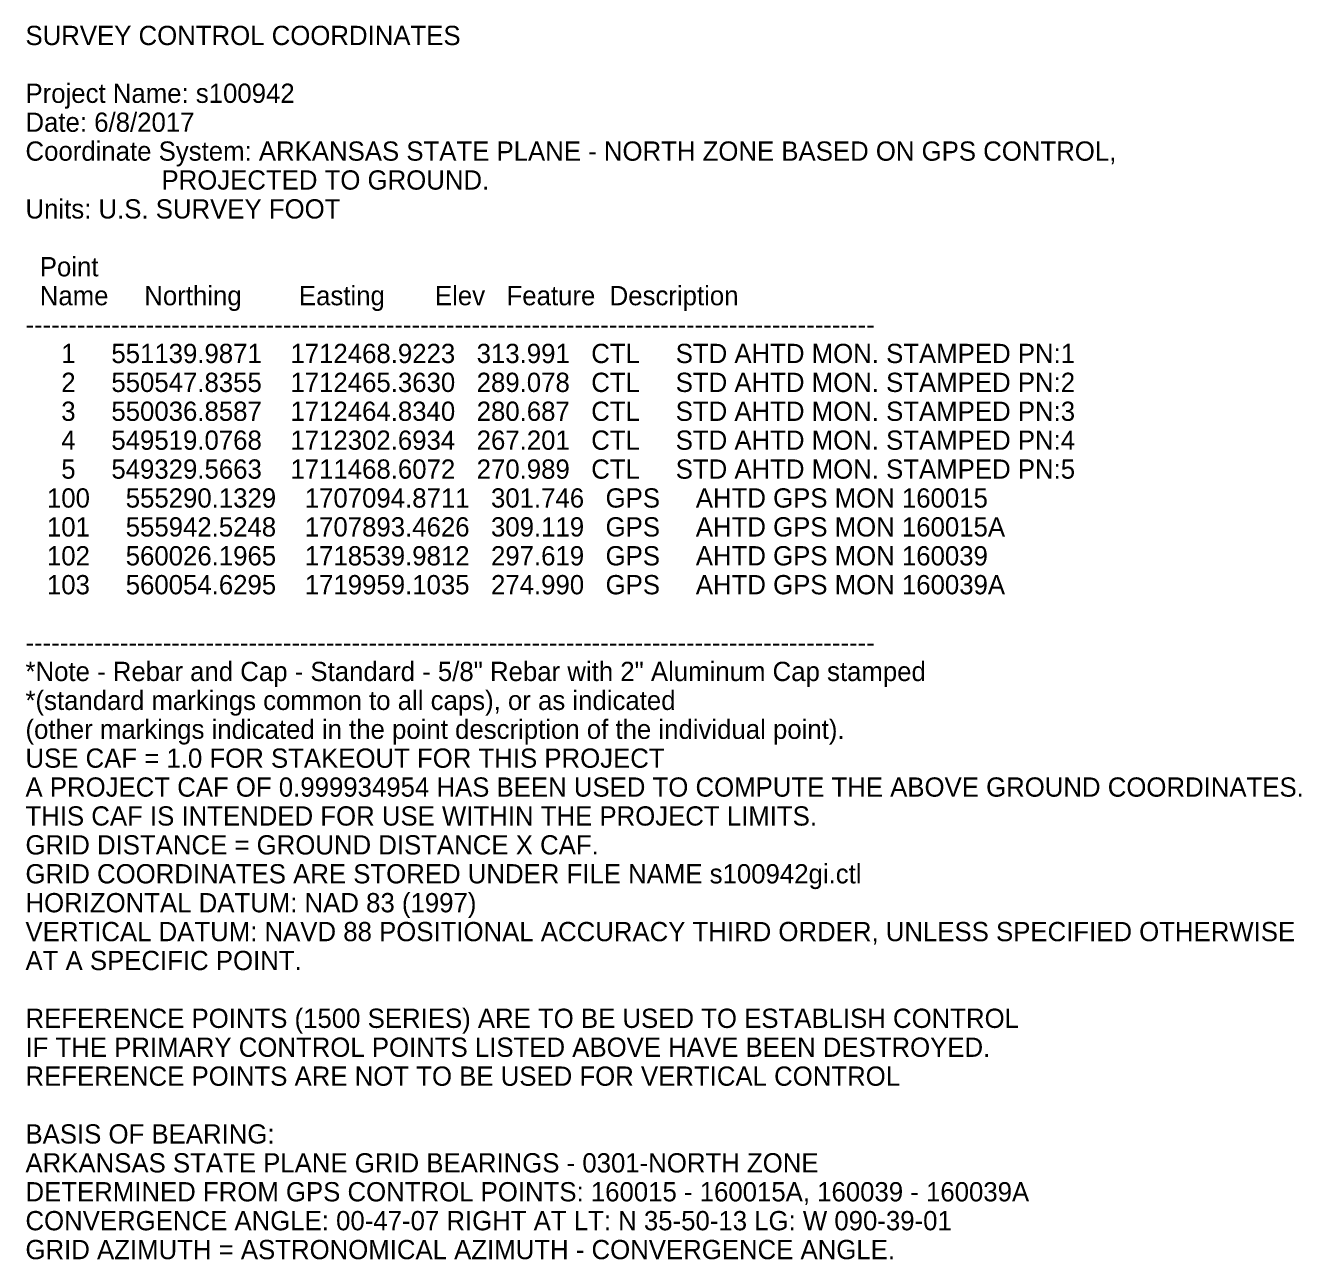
# Model space of a CAD drawing. Extents: x 1710417 to 1716352, y 548603 to 551217.
# Drawn here: x 1715804 to 1716352, y 550634 to 551164 of the extents above; entities that cross this region are included whole.
import ezdxf

# ---------------------------------------------------------------- set-up
doc = ezdxf.new("R2010")
doc.units = 0
doc.layers.add('Default', color=7, linetype='Continuous')

msp = doc.modelspace()

# ---------------------------------------------------------------- texts
at = {"layer": 'Default'}
for s, height, p in [('SURVEY CONTROL COORDINATES ', 8.2672, (1715804.01, 551155.33)), ('Project Name: s100942 ', 8.2672, (1715804.01, 551130.53)), ('Date: 6/8/2017 ', 8.2672, (1715804.01, 551118.13)), ('Coordinate System: ARKANSAS STATE PLANE - NORTH ZONE BASED ON GPS CONTROL, ', 8.2672, (1715804.01, 551105.73)), ('                   PROJECTED TO GROUND. ', 8.2672, (1715804.01, 551093.33)), ('Units: U.S. SURVEY FOOT ', 8.2672, (1715804.01, 551080.93)), ('  Point ', 8.267, (1715804.01, 551056.12)), ('  Name     Northing        Easting       Elev   Feature  Description ', 8.2672, (1715804.01, 551043.72)), ('--------------------------------------------------------------------------------------------------- ', 8.2672, (1715804.01, 551031.32)), ('     1     551139.9871    1712468.9223   313.991   CTL     STD AHTD MON. STAMPED PN:1 ', 8.2672, (1715804.01, 551018.92)), ('     2     550547.8355    1712465.3630   289.078   CTL     STD AHTD MON. STAMPED PN:2', 8.2672, (1715804.01, 551006.52)), ('     3     550036.8587    1712464.8340   280.687   CTL     STD AHTD MON. STAMPED PN:3', 8.2672, (1715804.01, 550994.12)), ('     4     549519.0768    1712302.6934   267.201   CTL     STD AHTD MON. STAMPED PN:4', 8.2672, (1715804.01, 550981.72)), ('     5     549329.5663    1711468.6072   270.989   CTL     STD AHTD MON. STAMPED PN:5 ', 8.2672, (1715804.01, 550969.32)), ('   100     555290.1329    1707094.8711   301.746   GPS     AHTD GPS MON 160015 ', 8.2672, (1715804.01, 550956.92)), ('   101     555942.5248    1707893.4626   309.119   GPS     AHTD GPS MON 160015A ', 8.2672, (1715804.01, 550944.52)), ('   102     560026.1965    1718539.9812   297.619   GPS     AHTD GPS MON 160039 ', 8.2672, (1715804.01, 550932.12)), ('   103     560054.6295    1719959.1035   274.990   GPS     AHTD GPS MON 160039A ', 8.2672, (1715804.01, 550919.72)), ('--------------------------------------------------------------------------------------------------- ', 8.2672, (1715804.01, 550894.92)), ('*Note - Rebar and Cap - Standard - 5/8" Rebar with 2" Aluminum Cap stamped ', 8.2672, (1715804.01, 550882.51)), ('*(standard markings common to all caps), or as indicated ', 8.2672, (1715804.01, 550870.11)), ('(other markings indicated in the point description of the individual point).  ', 8.2672, (1715804.01, 550857.71)), ('USE CAF = 1.0 FOR STAKEOUT FOR THIS PROJECT ', 8.2672, (1715804.01, 550845.31)), ('A PROJECT CAF OF 0.999934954 HAS BEEN USED TO COMPUTE THE ABOVE GROUND COORDINATES. ', 8.2672, (1715804.01, 550832.91)), ('THIS CAF IS INTENDED FOR USE WITHIN THE PROJECT LIMITS. ', 8.2672, (1715804.01, 550820.51)), ('GRID DISTANCE = GROUND DISTANCE X CAF. ', 8.2672, (1715804.01, 550808.11)), ('GRID COORDINATES ARE STORED UNDER FILE NAME s100942gi.ctl', 8.2672, (1715804.01, 550795.71)), ('HORIZONTAL DATUM: NAD 83 (1997) ', 8.2672, (1715804.01, 550783.31)), ('VERTICAL DATUM: NAVD 88 POSITIONAL ACCURACY THIRD ORDER, UNLESS SPECIFIED OTHERWISE  ', 8.2672, (1715804.01, 550770.91)), ('AT A SPECIFIC POINT. ', 8.2672, (1715804.01, 550758.51)), ('REFERENCE POINTS (1500 SERIES) ARE TO BE USED TO ESTABLISH CONTROL ', 8.2672, (1715804.01, 550733.71)), ('IF THE PRIMARY CONTROL POINTS LISTED ABOVE HAVE BEEN DESTROYED. ', 8.2672, (1715804.01, 550721.31)), ('REFERENCE POINTS ARE NOT TO BE USED FOR VERTICAL CONTROL ', 8.2672, (1715804.01, 550708.9)), ('BASIS OF BEARING: ', 8.2672, (1715804.01, 550684.1)), ('ARKANSAS STATE PLANE GRID BEARINGS - 0301-NORTH ZONE ', 8.2672, (1715804.01, 550671.7)), ('DETERMINED FROM GPS CONTROL POINTS: 160015 - 160015A, 160039 - 160039A', 8.2672, (1715804.01, 550659.3)), ('CONVERGENCE ANGLE: 00-47-07 RIGHT AT LT: N 35-50-13 LG: W 090-39-01', 8.2672, (1715804.01, 550646.9)), ('GRID AZIMUTH = ASTRONOMICAL AZIMUTH - CONVERGENCE ANGLE.', 8.2672, (1715804.01, 550634.5))]:
    msp.add_text(s, height=height, dxfattribs=at).set_placement(p)

doc.saveas('drawing.dxf')
